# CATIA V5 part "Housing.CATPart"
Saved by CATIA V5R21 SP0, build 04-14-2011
Part number: Housing
Bounding box of the stored display mesh (mm): x -219.226 to 234.489, y -581.07 to 15.616, z -219.336 to 219.336
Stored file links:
  C:\Users\riadm\Desktop\Jet_Engine\Housing.CATPart
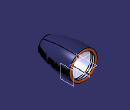
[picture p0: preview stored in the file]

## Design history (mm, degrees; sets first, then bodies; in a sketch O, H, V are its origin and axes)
Body1 (main body)
  Sketch1 on yz-plane, origin (0, 0, 0), H (0, 1, 0), V (0, 0, 1)
    arc A1 centre (-101.2236, -889.0639) radius 1108.558 from (-581.07, 110.26) to (0, 214.863) cw
    point P1 (-101.2236, -889.0639)
    point P2 (0, 214.863)
    point P3 (-581.07, 110.26)
    spline S1 through (0, 214.863) (15.616, 196.181) (0, 177.5)
    line L1 (0, 177.5) -> (-26.508, 177.5)
    line L2 (-26.508, 177.5) -> (-40.255, 187.5)
    line L3 (-40.255, 187.5) -> (-64.442, 187.5)
    point P6 (-64.442, 187.5)
    point P7 (0, 177.5)
    line L4 (-38.6288, 192.5) -> (-64.442, 192.5)
    line L5 (-38.6288, 192.5) -> (-24.8818, 182.5)
    line L6 (-1.4052, 182.5) -> (-24.8818, 182.5)
    frozenspline C1
    arc A2 centre (-101.2236, -889.0639) radius 1103.558 from (-1.6079, 209.9889) to (-578.9057, 105.7527) ccw
    line L7 (-64.442, 187.5) -> (-64.442, 192.5)
    line L8 (-581.07, 110.26) -> (-578.9057, 105.7527)
    point P14 (-581.07, 110.26)
    point P15 (0, 214.863)
    point P16 (0, 177.5)
    point P17 (15.616, 196.181)
    radius A1 = 1108.558
    distance P3 V = 581.07
    distance P3 H = 110.26
    distance P15 P17 V = 18.682
    distance P15 P16 = 37.363
    distance P16 P17 H = 15.616
    distance P6 H = 187.5
    length L1 = 26.508
    length L2 V = 10
    length L3 = 24.187
    distance P6 V = 64.442
    coincidence: P2 V, P15 P2, P16 V, P16 P7, P14 A1, L8 P1, P3 P14
    horizontal: L1 H, L3 H
    vertical: L7 V
  Shaft1: profile Sketch1, axis Sketch1.H, angle 360
Body2
  Plane1: type Offset, RefPlane yz-plane, Offset 250
  Sketch2 on Plane1, origin (250, 0, 0), H (0, 1, 0), V (0, 0, 1)
    polyline C1
    polyline C2
    polyline C3
    polyline C4
    polyline C5
    polyline C6
    polyline C7
    polyline C8
    polyline C9
    polyline C10
    polyline C11
  Pad1: profile Sketch2, direction (-1, 0, 0), up to face of Shaft1 from Sketch1.A1
  Sketch3 on yz-plane, origin (0, 0, 0), H (0, 1, 0), V (0, 0, 1)
    arc A1 centre (-101.2236, -889.0639) radius 1123.558 from (1.3697, 229.8003) to (-587.5628, 123.7819) ccw
    line L1 (1.3697, 229.8003) -> (1.3697, 689.7539)
    line L2 (1.3697, 689.7539) -> (-587.5628, 689.7539)
    line L3 (-587.5628, 689.7539) -> (-587.5628, 123.7819)
    vertical: L1 V, L3 V
    horizontal: L2 H
  Groove1: profile Sketch3, axis Sketch3.H, angle 360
